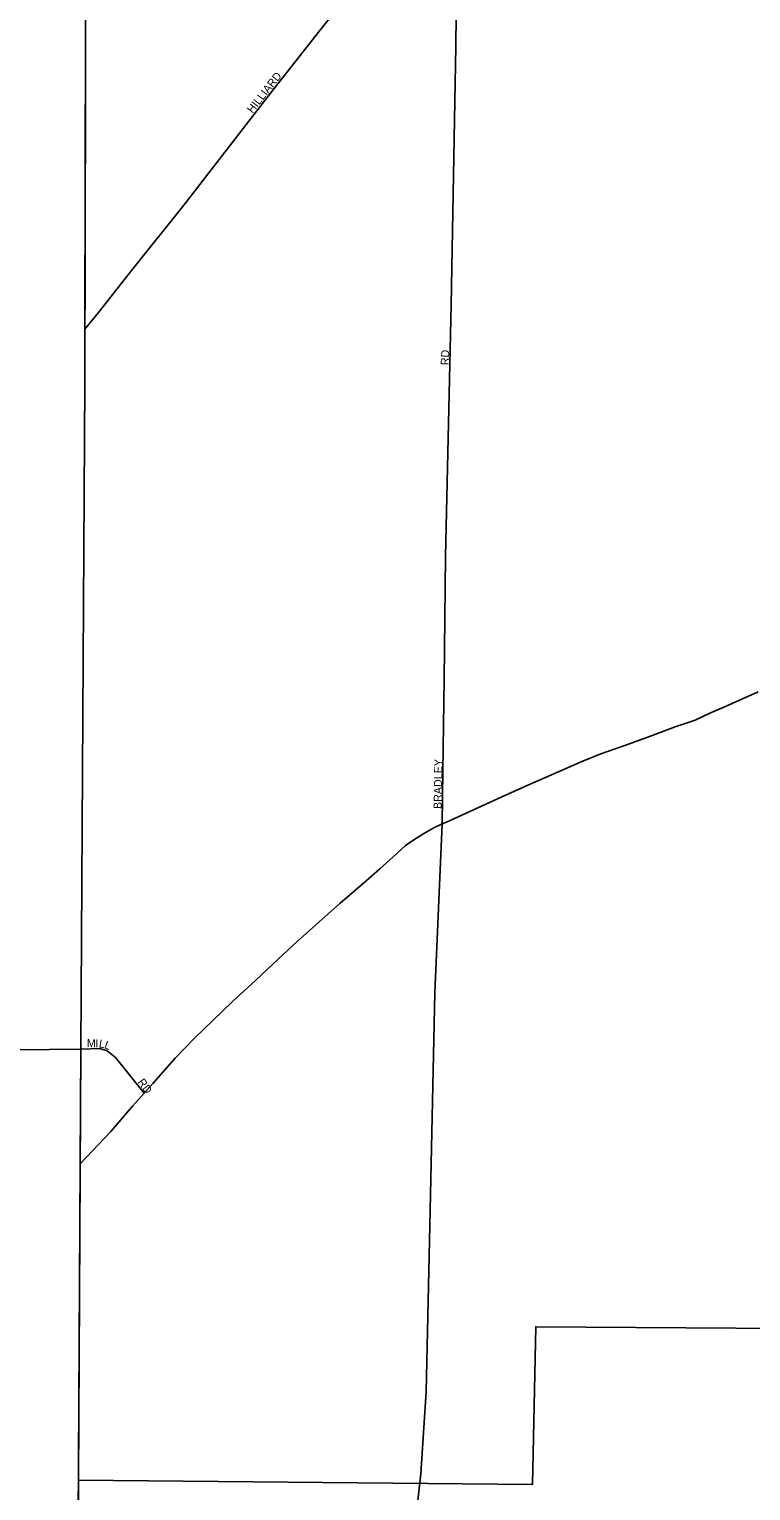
# Model space of a CAD drawing. Extents: x 2010165 to 2382125, y 1060529 to 1407316.
# Drawn here: x 2113583 to 2118094, y 1243150 to 1252283 of the extents above; entities that cross this region are included whole.
import ezdxf

# ---------------------------------------------------------------- set-up
doc = ezdxf.new("R2010")
doc.units = 0
for name, color, linetype in [('GM_X_Adjacent_County', 7, 'Continuous'), ('GM_X_City_Street', 7, 'Continuous'), ('GM_X_City_Street_Text', 7, 'Continuous'), ('GM_X_Corporation', 7, 'Continuous'), ('GM_X_County', 7, 'Continuous'), ('GM_X_US_Route', 7, 'Continuous')]:
    doc.layers.add(name, color=color, linetype=linetype)

msp = doc.modelspace()

# ---------------------------------------------------------------- linework, layer by layer
at = {"layer": 'GM_X_Adjacent_County'}
msp.add_lwpolyline([(2113953.5, 1260222.9), (2113939.6, 1254280.1), (2113939.3, 1254153.1), (2113930.6, 1250409.5), (2113929.8, 1250070.4), (2113906.2, 1245908.9), (2113902.2, 1245192.6), (2113878.9, 1241104.5)], dxfattribs=at)
at = {"layer": 'GM_X_City_Street'}
for points in [[(2113930.6, 1250409.5), (2114017, 1250513.8), (2114230.8, 1250786.6), (2114550.6, 1251183.8), (2115092.2, 1251883.9), (2115399.9, 1252275.1), (2115603.8, 1252531.8), (2115983.5, 1252963.2), (2116261.5, 1253143.9)], [(2116165.4, 1247317.2), (2116168.4, 1247646.2), (2116177.9, 1248219.4), (2116185.2, 1248989), (2116221.8, 1250560.3), (2116250.4, 1252177.8), (2116261.5, 1253143.9)], [(2116048.9, 1243513.1), (2116049.1, 1243515.2), (2116065.7, 1243768.1), (2116086.8, 1244808.3), (2116119.6, 1246261.3), (2116165.4, 1247317.2)], [(2113906.2, 1245908.9), (2114025.5, 1245914.4), (2114070.1, 1245900.1), (2114123.2, 1245858.2), (2114301.3, 1245634.1)], [(2113861.7, 1238095.7), (2113989.6, 1238240.8), (2114187.4, 1238497.6), (2114523.2, 1238906.7), (2114869, 1239311.9), (2115108.9, 1239548.7), (2115448.8, 1239833.6), (2115632.7, 1240002.1), (2115738.7, 1240094.4), (2115805.7, 1240157.8), (2115842.6, 1240222.8), (2115864.6, 1240272.9), (2115888.5, 1240331.1), (2115906.5, 1240389.2), (2115912.4, 1240485.4), (2115915.7, 1241323.1), (2115921.1, 1242034.5), (2115930.9, 1242297.1), (2115952.7, 1242517.5), (2115984.4, 1242832.2), (2116032.1, 1243257.1), (2116048.9, 1243513.1)]]:
    msp.add_lwpolyline(points, dxfattribs=at)
at = {"layer": 'GM_X_Corporation'}
for points in [[(2087103.1, 1267526.8), (2100292, 1267571.3), (2105566.3, 1267515.2), (2113972.1, 1267511.1), (2113971.4, 1267404), (2113929.8, 1250070.4), (2113906.2, 1245908.9), (2107567, 1245842.9), (2100580.4, 1245842), (2087018.7, 1245699)], [(2113906.2, 1245908.9), (2113890.9, 1243217.2), (2113849.1, 1234218.1), (2113829.3, 1229946.4), (2113744.8, 1221267.2), (2112015.1, 1221289.3), (2108462.7, 1221311.6), (2108435.6, 1221318.7), (2108389.2, 1221316.1), (2108204.3, 1221319.4), (2095838.9, 1221294.6), (2094008.8, 1221306.3), (2090317.5, 1221329.8), (2090283.5, 1221329.8), (2090249.5, 1221329.8), (2087936.7, 1221317.6), (2086892.2, 1221272.8), (2087018.7, 1245699), (2100580.4, 1245842), (2107567, 1245842.9)]]:
    msp.add_lwpolyline(points, close=True, dxfattribs=at)
for points in [[(2132230.3, 1251466.2), (2124149.1, 1251538.9), (2124088.2, 1249725.4), (2123111, 1249688.7), (2123195.5, 1249602.9), (2122407.5, 1248826.9), (2122369.9, 1248724.5), (2121430.7, 1248710), (2121435.6, 1245924.1), (2120624.6, 1245916.3), (2120503.3, 1244150.8), (2116750.2, 1244175.2), (2116730.1, 1243190.3), (2113890.9, 1243217.2), (2113906.2, 1245908.9), (2113929.8, 1250070.4), (2113971.4, 1267404)], [(2132680.2, 1238887), (2124751.5, 1238922.2), (2124734, 1236210.6), (2124291.4, 1236212.5), (2123784.7, 1236210.1), (2121079.3, 1236231.2), (2121079, 1235091.9), (2120094.3, 1235126), (2120087.8, 1234155), (2113849.1, 1234218.1), (2113890.9, 1243217.2), (2116730.1, 1243190.3), (2116750.2, 1244175.2), (2120503.3, 1244150.8), (2120624.6, 1245916.3), (2121435.6, 1245924.1), (2121430.7, 1248710), (2122369.9, 1248724.5), (2122407.5, 1248826.9), (2123195.5, 1249602.9), (2123111, 1249688.7), (2124088.2, 1249725.4), (2124149.1, 1251538.9), (2132230.3, 1251466.2)]]:
    msp.add_lwpolyline(points, dxfattribs=at)
at = {"layer": 'GM_X_County'}
msp.add_lwpolyline([(2113878.9, 1241104.5), (2113902.2, 1245192.6), (2113906.2, 1245908.9), (2113929.8, 1250070.4), (2113930.6, 1250409.5), (2113939.3, 1254153.1), (2113939.6, 1254280.1), (2113953.5, 1260222.9)], dxfattribs=at)
at = {"layer": 'GM_X_US_Route'}
msp.add_lwpolyline([(2113902.2, 1245192.6), (2114093.4, 1245395.1), (2114229.6, 1245553.4), (2114301.3, 1245634.1), (2114355.9, 1245695.7), (2114496.1, 1245854), (2114616.3, 1245978.3), (2114730.5, 1246088.5), (2114854.7, 1246206.8), (2114997, 1246339), (2115141.2, 1246475.3), (2115257.4, 1246583.5), (2115393.7, 1246703.8), (2115527.9, 1246822), (2115670.1, 1246944.3), (2115774.3, 1247036.5), (2115878.5, 1247130.7), (2115936.6, 1247182.8), (2115986.7, 1247218.8), (2116050.8, 1247256.9), (2116112.9, 1247293), (2116165.4, 1247317.2), (2116191, 1247329.1), (2116337.3, 1247395.2), (2116533.6, 1247485.3), (2116699.9, 1247559.5), (2116882.2, 1247639.6), (2117034.4, 1247705.7), (2117156.7, 1247755.8), (2117306.9, 1247807.9), (2117461.2, 1247864), (2117621.4, 1247924.1), (2117745.6, 1247966.2), (2117837.8, 1248010.3), (2117940, 1248052.4), (2118042.1, 1248098.4), (2118140.3, 1248142.5)], dxfattribs=at)

# ---------------------------------------------------------------- texts
at = {"layer": 'GM_X_City_Street_Text'}
for s, rotation, p in [('HILLIARD', 51.74672, (2114978.8, 1251754)), ('RD', 86.98328, (2116205.2, 1250182.4)), ('BRADLEY', 89.13078, (2116161.2, 1247410.1)), ('M', 359.18037, (2113943.4, 1245922.7)), ('I', 359.16937, (2113996.2, 1245922)), ('L', 350.4209, (2114016.2, 1245921.8)), ('L', 340.55845, (2114048.7, 1245916.6)), ('RD', 306.25416, (2114258.6, 1245703.5))]:
    msp.add_text(s, height=50, rotation=rotation, dxfattribs=at).set_placement(p)

doc.saveas('drawing.dxf')
